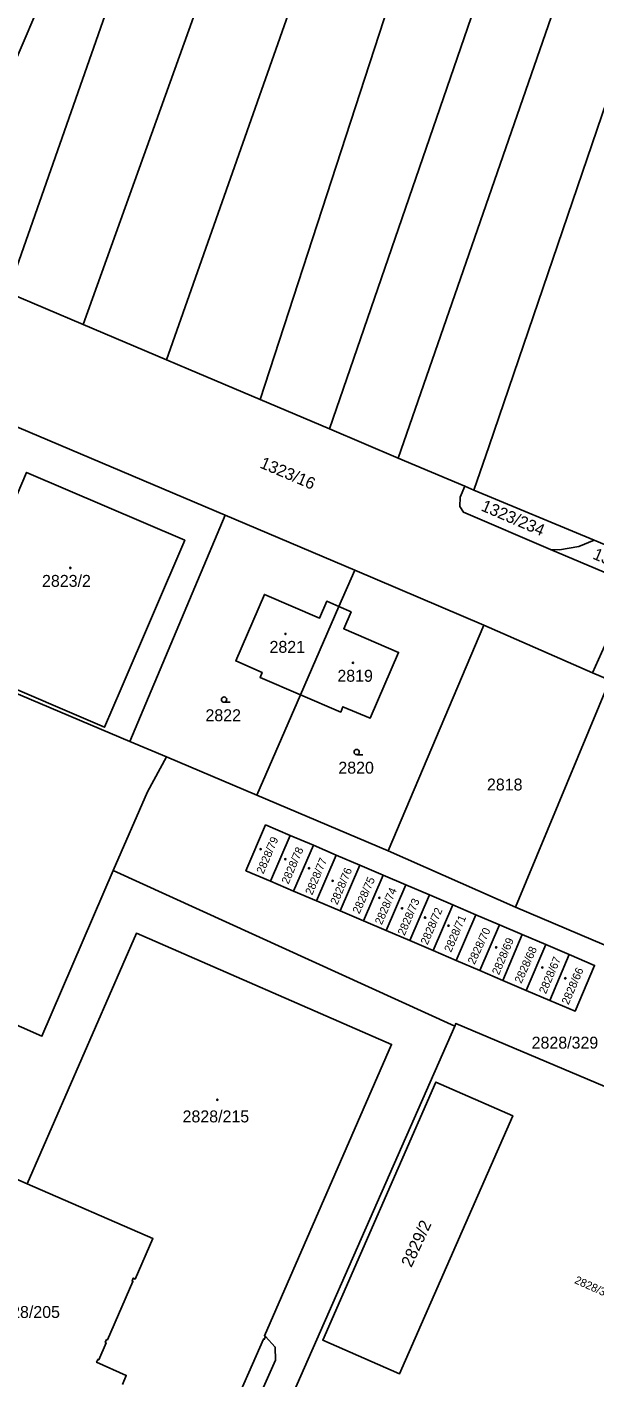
# Model space of a CAD drawing. Extents: x -596024 to -594475, y -1163820 to -1161957.
# Drawn here: x -594849.5 to -594768.7, y -1162300.1 to -1162107.7 of the extents above; entities that cross this region are included whole.
import ezdxf

# ---------------------------------------------------------------- set-up
doc = ezdxf.new("R2010")
doc.units = 0
for name, color, linetype in [('Level 1', 7, 'Continuous'), ('Level 4', 7, 'Continuous'), ('Level 5', 7, 'Continuous'), ('Level 60', 7, 'Continuous'), ('Vrstva 60', 7, 'Continuous')]:
    doc.layers.add(name, color=color, linetype=linetype)

msp = doc.modelspace()

# ---------------------------------------------------------------- linework, layer by layer
at = {"layer": 'Level 1'}
for points in [[(-594841.52, -1162150.04), (-594806.77, -1162053.21), (-594778.96, -1161974.89)], [(-594829.67, -1162155.07), (-594795.88, -1162059.09), (-594768.31, -1161981.07)], [(-594852.23, -1162145.49), (-594817.81, -1162047.12), (-594795.84, -1161983.5)], [(-594756.96, -1161987.43), (-594785.13, -1162064.92), (-594816.34, -1162160.73)], [(-594806.44, -1162164.93), (-594773.98, -1162070.58), (-594746.76, -1161991.96)], [(-594736.99, -1161996.29), (-594764.38, -1162075.96), (-594796.68, -1162169.08)], [(-594785.91, -1162173.65), (-594783.72, -1162167.34), (-594755.8, -1162085.45), (-594725.97, -1162001.77)], [(-594857.29, -1162126.68), (-594809.23, -1162014.4)], [(-594841.52, -1162150.04), (-594852.23, -1162145.49)], [(-594829.67, -1162155.07), (-594841.52, -1162150.04)], [(-594816.34, -1162160.73), (-594826.54, -1162156.4), (-594829.67, -1162155.07)], [(-594806.44, -1162164.93), (-594816.34, -1162160.73)], [(-594821.3, -1162177.21), (-594858.18, -1162161.58)], [(-594796.68, -1162169.08), (-594806.44, -1162164.93)], [(-594787.2, -1162173.1), (-594796.68, -1162169.08)], [(-594864.86, -1162177.56), (-594854.28, -1162182.09), (-594849.59, -1162171.14), (-594827.06, -1162180.8), (-594836.11, -1162201.91), (-594838.47, -1162207.42), (-594855.25, -1162200.24), (-594852.89, -1162194.72), (-594858.64, -1162192.26), (-594869.13, -1162187.77)], [(-594774.97, -1162182.11), (-594787.37, -1162176.81), (-594787.91, -1162175.99), (-594787.84, -1162174.66), (-594787.2, -1162173.1)], [(-594785.91, -1162173.65), (-594787.2, -1162173.1)], [(-594768.79, -1162180.79), (-594785.91, -1162173.65)], [(-594834.89, -1162209.45), (-594821.3, -1162177.21)], [(-594802.86, -1162185.03), (-594821.3, -1162177.21)], [(-594774.97, -1162182.11), (-594773.7, -1162182.16), (-594770.94, -1162181.7), (-594768.79, -1162180.79)], [(-594774.97, -1162182.11), (-594753.62, -1162191.15)], [(-594757.22, -1162185.61), (-594768.79, -1162180.79)], [(-594805.13, -1162190.23), (-594802.86, -1162185.03)], [(-594802.86, -1162185.03), (-594784.49, -1162192.89)], [(-594805.13, -1162190.23), (-594806.84, -1162189.49), (-594807.88, -1162191.9), (-594815.71, -1162188.51), (-594819.79, -1162197.99), (-594816.04, -1162199.63), (-594816.33, -1162200.32), (-594810.59, -1162202.79)], [(-594810.59, -1162202.79), (-594804.85, -1162205.26), (-594804.54, -1162204.52), (-594800.67, -1162206.15), (-594796.61, -1162196.78), (-594804.42, -1162193.4), (-594803.38, -1162190.99), (-594805.13, -1162190.23)], [(-594810.59, -1162202.79), (-594805.13, -1162190.23)], [(-594871.68, -1162193.87), (-594834.89, -1162209.45)], [(-594798.1, -1162225.02), (-594784.49, -1162192.89)], [(-594784.49, -1162192.89), (-594768.99, -1162199.68)], [(-594707.09, -1162223.48), (-594736.5, -1162210.95), (-594743.11, -1162207.81), (-594746.4, -1162206.15), (-594756.91, -1162200.41), (-594760.53, -1162198.75), (-594767.3, -1162195.88), (-594768.99, -1162199.68)], [(-594768.99, -1162199.68), (-594766.55, -1162200.72)], [(-594779.95, -1162233.06), (-594766.55, -1162200.72)], [(-594816.82, -1162217.1), (-594810.59, -1162202.79)], [(-594834.89, -1162209.45), (-594829.67, -1162211.66)], [(-594829.67, -1162211.66), (-594832.36, -1162216.61), (-594837.24, -1162227.82)], [(-594829.67, -1162211.66), (-594816.82, -1162217.1)], [(-594816.82, -1162217.1), (-594798.1, -1162225.02)], [(-594814.87, -1162229.35), (-594818.34, -1162227.87), (-594815.55, -1162221.34), (-594812.07, -1162222.84)], [(-594814.87, -1162229.35), (-594812.07, -1162222.84)], [(-594812.07, -1162222.84), (-594808.75, -1162224.24)], [(-594808.75, -1162224.24), (-594811.56, -1162230.76)], [(-594808.75, -1162224.24), (-594805.49, -1162225.64)], [(-594808.28, -1162232.16), (-594805.49, -1162225.64)], [(-594805.49, -1162225.64), (-594802.14, -1162227.07)], [(-594798.1, -1162225.02), (-594779.95, -1162233.06)], [(-594837.24, -1162227.82), (-594847.4, -1162251.46), (-594868.17, -1162242.29)], [(-594788.63, -1162249.99), (-594837.24, -1162227.82)], [(-594802.14, -1162227.07), (-594804.94, -1162233.59)], [(-594802.14, -1162227.07), (-594798.79, -1162228.51)], [(-594801.59, -1162235.02), (-594798.79, -1162228.51)], [(-594798.79, -1162228.51), (-594795.57, -1162229.88)], [(-594814.87, -1162229.35), (-594811.56, -1162230.76)], [(-594795.57, -1162229.88), (-594798.37, -1162236.4)], [(-594795.57, -1162229.88), (-594792.22, -1162231.31)], [(-594811.56, -1162230.76), (-594808.28, -1162232.16)], [(-594808.28, -1162232.16), (-594804.94, -1162233.59)], [(-594795.02, -1162237.83), (-594792.22, -1162231.31)], [(-594792.22, -1162231.31), (-594788.91, -1162232.73)], [(-594804.94, -1162233.59), (-594801.59, -1162235.02)], [(-594788.91, -1162232.73), (-594791.71, -1162239.25)], [(-594788.91, -1162232.73), (-594785.6, -1162234.14)], [(-594788.4, -1162240.66), (-594785.6, -1162234.14)], [(-594785.6, -1162234.14), (-594782.25, -1162235.57)], [(-594779.95, -1162233.06), (-594749.03, -1162246.2)], [(-594801.59, -1162235.02), (-594798.37, -1162236.4)], [(-594782.25, -1162235.57), (-594785.05, -1162242.09)], [(-594782.25, -1162235.57), (-594779, -1162236.97)], [(-594849.48, -1162272.49), (-594833.95, -1162236.78), (-594797.61, -1162252.61), (-594815.72, -1162294.12), (-594815.54, -1162294.21)], [(-594798.37, -1162236.4), (-594795.02, -1162237.83)], [(-594795.02, -1162237.83), (-594791.71, -1162239.25)], [(-594781.78, -1162243.49), (-594779, -1162236.97)], [(-594779, -1162236.97), (-594775.64, -1162238.4)], [(-594791.71, -1162239.25), (-594788.4, -1162240.66)], [(-594775.64, -1162238.4), (-594778.43, -1162244.92)], [(-594775.64, -1162238.4), (-594772.31, -1162239.82)], [(-594775.1, -1162246.34), (-594771.49, -1162247.88), (-594768.7, -1162241.36), (-594772.31, -1162239.82)], [(-594775.1, -1162246.34), (-594772.31, -1162239.82)], [(-594788.4, -1162240.66), (-594785.05, -1162242.09)], [(-594785.05, -1162242.09), (-594781.78, -1162243.49)], [(-594781.78, -1162243.49), (-594778.43, -1162244.92)], [(-594778.43, -1162244.92), (-594775.1, -1162246.34)], [(-594715.61, -1162280.43), (-594788.46, -1162249.61), (-594788.63, -1162249.99)], [(-594821.58, -1162324.95), (-594788.63, -1162249.99)], [(-594791.3, -1162257.98), (-594780.37, -1162262.77), (-594796.5, -1162299.54), (-594807.41, -1162294.75), (-594791.3, -1162257.98)], [(-594885.3, -1162282.79), (-594867.51, -1162290.26), (-594864.86, -1162290.92), (-594862.22, -1162289.83), (-594860.52, -1162287.62), (-594853.15, -1162270.88), (-594849.48, -1162272.49)], [(-594835.91, -1162301.05), (-594835.38, -1162299.76), (-594839.62, -1162297.9), (-594839.44, -1162297.49), (-594839.3, -1162297.55), (-594838.25, -1162295.12), (-594838.38, -1162295.06), (-594838.2, -1162294.65), (-594838.06, -1162294.71), (-594834.45, -1162286.38), (-594834.57, -1162286.32), (-594834.39, -1162285.91), (-594834.12, -1162286.03), (-594831.6, -1162280.27), (-594849.48, -1162272.49)], [(-594815.54, -1162294.21), (-594814.18, -1162295.74), (-594814.16, -1162297.59), (-594818.13, -1162306.56), (-594819.84, -1162308.09), (-594821.5, -1162308.69), (-594823.27, -1162309.05), (-594824.81, -1162308.95), (-594816.8, -1162312.43), (-594821.23, -1162322.49), (-594846.15, -1162311.6), (-594844.17, -1162307.04), (-594846.11, -1162306.5), (-594848.19, -1162306.39), (-594850.17, -1162306.87), (-594851.94, -1162307.88), (-594853.68, -1162309.72), (-594854.4, -1162311.13)], [(-594815.54, -1162294.21), (-594815.74, -1162294.63), (-594815.85, -1162294.58), (-594820.73, -1162305.71)]]:
    msp.add_lwpolyline(points, dxfattribs=at)
at = {"layer": 'Level 5'}
for p, q in [((-594821.46, -1162203.87), (-594820.58, -1162203.87)), ((-594802.58, -1162211.34), (-594801.7, -1162211.34))]:
    msp.add_line(p, q, dxfattribs=at)
for centre, radius in [((-594843.35, -1162184.73), 0.09), ((-594843.35, -1162184.73), 0.0521), ((-594812.71, -1162194.13), 0.09), ((-594812.71, -1162194.13), 0.0521), ((-594803.12, -1162198.25), 0.09), ((-594803.12, -1162198.25), 0.0521), ((-594821.46, -1162203.49), 0.375), ((-594802.58, -1162210.96), 0.375), ((-594816.25, -1162224.8), 0.09), ((-594816.25, -1162224.8), 0.0521), ((-594812.73, -1162226.22), 0.09), ((-594812.73, -1162226.22), 0.0521), ((-594809.37, -1162227.52), 0.09), ((-594809.37, -1162227.52), 0.0521), ((-594806, -1162229.31), 0.09), ((-594806, -1162229.31), 0.0521), ((-594799.36, -1162231.73), 0.09), ((-594799.36, -1162231.73), 0.0521), ((-594796.12, -1162233.23), 0.09), ((-594796.12, -1162233.23), 0.0521), ((-594792.84, -1162234.54), 0.09), ((-594792.84, -1162234.54), 0.0521), ((-594789.51, -1162235.71), 0.09), ((-594789.51, -1162235.71), 0.0521), ((-594782.72, -1162238.79), 0.09), ((-594782.72, -1162238.79), 0.0521), ((-594776.14, -1162241.66), 0.09), ((-594776.14, -1162241.66), 0.0521), ((-594772.88, -1162243.19), 0.09), ((-594772.88, -1162243.19), 0.0521), ((-594822.42, -1162260.5), 0.09), ((-594822.42, -1162260.5), 0.0521)]:
    msp.add_circle(centre, radius, dxfattribs=at)
at = {"layer": 'Level 60'}
for points in [[(-594806.77, -1162053.21), (-594841.52, -1162150.04), (-594852.23, -1162145.49), (-594817.81, -1162047.12), (-594795.84, -1161983.5), (-594789.11, -1161967.85), (-594778.96, -1161974.89)], [(-594795.88, -1162059.09), (-594829.67, -1162155.07), (-594841.52, -1162150.04), (-594806.77, -1162053.21), (-594778.96, -1161974.89), (-594768.31, -1161981.07)], [(-594768.31, -1161981.07), (-594756.96, -1161987.43), (-594785.13, -1162064.92), (-594816.34, -1162160.73), (-594826.54, -1162156.4), (-594829.67, -1162155.07), (-594795.88, -1162059.09)], [(-594817.81, -1162047.12), (-594852.23, -1162145.49), (-594862.25, -1162141.24), (-594857.29, -1162126.68), (-594809.23, -1162014.4), (-594795.84, -1161983.5)], [(-594806.44, -1162164.93), (-594816.34, -1162160.73), (-594785.13, -1162064.92), (-594756.96, -1161987.43), (-594746.76, -1161991.96), (-594773.98, -1162070.58)], [(-594736.99, -1161996.29), (-594764.38, -1162075.96), (-594796.68, -1162169.08), (-594806.44, -1162164.93), (-594773.98, -1162070.58), (-594746.76, -1161991.96)], [(-594861.45, -1162136.02), (-594935.08, -1162105.7), (-594930.49, -1162089.91), (-594898.57, -1162015.96), (-594890.22, -1161996.88), (-594874.7, -1162003.85), (-594838.41, -1162020.17), (-594830.59, -1162006.94), (-594829.79, -1162005.61), (-594809.23, -1162014.4), (-594857.29, -1162126.68)], [(-594755.8, -1162085.45), (-594783.72, -1162167.34), (-594785.91, -1162173.65), (-594787.2, -1162173.1), (-594796.68, -1162169.08), (-594764.38, -1162075.96), (-594736.99, -1161996.29), (-594725.97, -1162001.77)], [(-594783.72, -1162167.34), (-594755.8, -1162085.45), (-594725.97, -1162001.77), (-594686.86, -1162020.42), (-594715.97, -1162103.7), (-594744.22, -1162183.48), (-594746.55, -1162190.06), (-594757.22, -1162185.61), (-594768.79, -1162180.79), (-594785.91, -1162173.65)], [(-594827.06, -1162180.8), (-594849.59, -1162171.14), (-594854.28, -1162182.09), (-594864.86, -1162177.56), (-594858.18, -1162161.58), (-594821.3, -1162177.21), (-594834.89, -1162209.45), (-594871.68, -1162193.87), (-594869.13, -1162187.77), (-594858.64, -1162192.26), (-594852.89, -1162194.72), (-594855.25, -1162200.24), (-594838.47, -1162207.42), (-594836.11, -1162201.91)], [(-594849.59, -1162171.14), (-594827.06, -1162180.8), (-594836.11, -1162201.91), (-594838.47, -1162207.42), (-594855.25, -1162200.24), (-594852.89, -1162194.72), (-594858.64, -1162192.26), (-594869.13, -1162187.77), (-594864.86, -1162177.56), (-594854.28, -1162182.09)], [(-594787.37, -1162176.81), (-594787.91, -1162175.99), (-594787.84, -1162174.66), (-594787.2, -1162173.1), (-594785.91, -1162173.65), (-594768.79, -1162180.79), (-594770.94, -1162181.7), (-594773.7, -1162182.16), (-594774.97, -1162182.11)], [(-594871.68, -1162193.87), (-594834.89, -1162209.45), (-594829.67, -1162211.66), (-594832.36, -1162216.61), (-594837.24, -1162227.82), (-594847.4, -1162251.46), (-594868.17, -1162242.29), (-594910.96, -1162223.4), (-594905.52, -1162210.83), (-594912.71, -1162195.25), (-594916.76, -1162183.81), (-594914.71, -1162178.11)], [(-594815.71, -1162188.51), (-594819.79, -1162197.99), (-594816.04, -1162199.63), (-594816.33, -1162200.32), (-594810.59, -1162202.79), (-594816.82, -1162217.1), (-594829.67, -1162211.66), (-594834.89, -1162209.45), (-594821.3, -1162177.21), (-594802.86, -1162185.03), (-594805.13, -1162190.23), (-594806.84, -1162189.49), (-594807.88, -1162191.9)], [(-594774.97, -1162182.11), (-594773.7, -1162182.16), (-594770.94, -1162181.7), (-594768.79, -1162180.79), (-594757.22, -1162185.61), (-594757.06, -1162186.25), (-594755.77, -1162188.82), (-594753.62, -1162191.15)], [(-594804.85, -1162205.26), (-594804.54, -1162204.52), (-594800.67, -1162206.15), (-594796.61, -1162196.78), (-594804.42, -1162193.4), (-594803.38, -1162190.99), (-594805.13, -1162190.23), (-594802.86, -1162185.03), (-594784.49, -1162192.89), (-594798.1, -1162225.02), (-594816.82, -1162217.1), (-594810.59, -1162202.79)], [(-594819.79, -1162197.99), (-594815.71, -1162188.51), (-594807.88, -1162191.9), (-594806.84, -1162189.49), (-594805.13, -1162190.23), (-594810.59, -1162202.79), (-594816.33, -1162200.32), (-594816.04, -1162199.63)], [(-594804.54, -1162204.52), (-594804.85, -1162205.26), (-594810.59, -1162202.79), (-594805.13, -1162190.23), (-594803.38, -1162190.99), (-594804.42, -1162193.4), (-594796.61, -1162196.78), (-594800.67, -1162206.15)], [(-594784.49, -1162192.89), (-594768.99, -1162199.68), (-594766.55, -1162200.72), (-594779.95, -1162233.06), (-594798.1, -1162225.02)], [(-594702.53, -1162225.59), (-594699.9, -1162227.48), (-594697.92, -1162229.81), (-594735.81, -1162213.85), (-594766.55, -1162200.72), (-594768.99, -1162199.68), (-594767.3, -1162195.88), (-594760.53, -1162198.75), (-594756.91, -1162200.41), (-594746.4, -1162206.15), (-594743.11, -1162207.81), (-594736.5, -1162210.95), (-594707.09, -1162223.48)], [(-594735.81, -1162213.85), (-594736.56, -1162215.7), (-594749.03, -1162246.2), (-594779.95, -1162233.06), (-594766.55, -1162200.72)], [(-594816.82, -1162217.1), (-594798.1, -1162225.02), (-594779.95, -1162233.06), (-594749.03, -1162246.2), (-594708.5, -1162263.93), (-594715.61, -1162280.43), (-594788.46, -1162249.61), (-594788.63, -1162249.99), (-594837.24, -1162227.82), (-594832.36, -1162216.61), (-594829.67, -1162211.66)], [(-594818.34, -1162227.87), (-594814.87, -1162229.35), (-594811.56, -1162230.76), (-594808.28, -1162232.16), (-594804.94, -1162233.59), (-594801.59, -1162235.02), (-594798.37, -1162236.4), (-594795.02, -1162237.83), (-594791.71, -1162239.25), (-594788.4, -1162240.66), (-594785.05, -1162242.09), (-594781.78, -1162243.49), (-594778.43, -1162244.92), (-594775.1, -1162246.34), (-594771.49, -1162247.88), (-594768.7, -1162241.36), (-594772.31, -1162239.82), (-594775.64, -1162238.4), (-594779, -1162236.97), (-594782.25, -1162235.57), (-594785.6, -1162234.14), (-594788.91, -1162232.73), (-594792.22, -1162231.31), (-594795.57, -1162229.88), (-594798.79, -1162228.51), (-594802.14, -1162227.07), (-594805.49, -1162225.64), (-594808.75, -1162224.24), (-594812.07, -1162222.84), (-594815.55, -1162221.34)], [(-594812.07, -1162222.84), (-594814.87, -1162229.35), (-594818.34, -1162227.87), (-594815.55, -1162221.34)], [(-594808.75, -1162224.24), (-594811.56, -1162230.76), (-594814.87, -1162229.35), (-594812.07, -1162222.84)], [(-594805.49, -1162225.64), (-594808.28, -1162232.16), (-594811.56, -1162230.76), (-594808.75, -1162224.24)], [(-594802.14, -1162227.07), (-594804.94, -1162233.59), (-594808.28, -1162232.16), (-594805.49, -1162225.64)], [(-594798.79, -1162228.51), (-594801.59, -1162235.02), (-594804.94, -1162233.59), (-594802.14, -1162227.07)], [(-594795.57, -1162229.88), (-594798.37, -1162236.4), (-594801.59, -1162235.02), (-594798.79, -1162228.51)], [(-594792.22, -1162231.31), (-594795.02, -1162237.83), (-594798.37, -1162236.4), (-594795.57, -1162229.88)], [(-594788.91, -1162232.73), (-594791.71, -1162239.25), (-594795.02, -1162237.83), (-594792.22, -1162231.31)], [(-594785.6, -1162234.14), (-594788.4, -1162240.66), (-594791.71, -1162239.25), (-594788.91, -1162232.73)], [(-594782.25, -1162235.57), (-594785.05, -1162242.09), (-594788.4, -1162240.66), (-594785.6, -1162234.14)], [(-594779, -1162236.97), (-594781.78, -1162243.49), (-594785.05, -1162242.09), (-594782.25, -1162235.57)], [(-594775.64, -1162238.4), (-594778.43, -1162244.92), (-594781.78, -1162243.49), (-594779, -1162236.97)], [(-594772.31, -1162239.82), (-594775.1, -1162246.34), (-594778.43, -1162244.92), (-594775.64, -1162238.4)], [(-594775.1, -1162246.34), (-594772.31, -1162239.82), (-594768.7, -1162241.36), (-594771.49, -1162247.88)], [(-594788.46, -1162249.61), (-594715.61, -1162280.43), (-594744.57, -1162347.6), (-594746.96, -1162353.57), (-594748.04, -1162354.24), (-594750.51, -1162354.75), (-594752.49, -1162354.29), (-594804.19, -1162332.35), (-594810.1, -1162329.79), (-594821.58, -1162324.95), (-594788.63, -1162249.99)], [(-594780.37, -1162262.77), (-594791.3, -1162257.98), (-594807.41, -1162294.75), (-594796.5, -1162299.54)], [(-594791.3, -1162257.98), (-594780.37, -1162262.77), (-594796.5, -1162299.54), (-594807.41, -1162294.75)]]:
    msp.add_lwpolyline(points, close=True, dxfattribs=at)
for points in [[(-594868.17, -1162242.29), (-594847.4, -1162251.46), (-594837.24, -1162227.82), (-594788.63, -1162249.99), (-594821.58, -1162324.95), (-594854.4, -1162311.13)], [(-594850.17, -1162306.87), (-594848.19, -1162306.39), (-594846.11, -1162306.5), (-594844.17, -1162307.04), (-594846.15, -1162311.6), (-594821.23, -1162322.49), (-594816.8, -1162312.43), (-594824.81, -1162308.95), (-594823.27, -1162309.05), (-594821.5, -1162308.69), (-594819.84, -1162308.09), (-594818.13, -1162306.56), (-594814.16, -1162297.59), (-594814.18, -1162295.74), (-594815.54, -1162294.21), (-594815.72, -1162294.12), (-594797.61, -1162252.61), (-594833.95, -1162236.78), (-594849.48, -1162272.49), (-594853.15, -1162270.88)], [(-594835.91, -1162301.05), (-594835.38, -1162299.76), (-594839.62, -1162297.9), (-594839.44, -1162297.49), (-594839.3, -1162297.55), (-594838.25, -1162295.12), (-594838.38, -1162295.06), (-594838.2, -1162294.65), (-594838.06, -1162294.71), (-594834.45, -1162286.38), (-594834.57, -1162286.32), (-594834.39, -1162285.91), (-594834.12, -1162286.03), (-594831.6, -1162280.27), (-594849.48, -1162272.49), (-594833.95, -1162236.78), (-594797.61, -1162252.61), (-594815.72, -1162294.12), (-594815.54, -1162294.21), (-594815.74, -1162294.63), (-594815.85, -1162294.58), (-594820.73, -1162305.71)], [(-594853.15, -1162270.88), (-594849.48, -1162272.49), (-594831.6, -1162280.27), (-594834.12, -1162286.03), (-594834.39, -1162285.91), (-594834.57, -1162286.32), (-594834.45, -1162286.38), (-594838.06, -1162294.71), (-594838.2, -1162294.65), (-594838.38, -1162295.06), (-594838.25, -1162295.12), (-594839.3, -1162297.55), (-594839.44, -1162297.49), (-594839.62, -1162297.9), (-594835.38, -1162299.76), (-594835.91, -1162301.05)], [(-594820.73, -1162305.71), (-594815.85, -1162294.58), (-594815.74, -1162294.63), (-594815.54, -1162294.21), (-594814.18, -1162295.74), (-594814.16, -1162297.59), (-594818.13, -1162306.56)]]:
    msp.add_lwpolyline(points, dxfattribs=at)
at = {"layer": 'Vrstva 60'}
for points in [[(-594629.59, -1162242.59), (-594657.76, -1162230.53), (-594675.03, -1162223.23), (-594709.6, -1162209.52), (-594727.84, -1162201.98), (-594745.73, -1162194.48), (-594753.62, -1162191.15), (-594774.97, -1162182.11), (-594787.37, -1162176.81), (-594787.91, -1162175.99), (-594787.84, -1162174.66), (-594787.2, -1162173.1), (-594796.68, -1162169.08), (-594806.44, -1162164.93), (-594816.34, -1162160.73), (-594826.54, -1162156.4), (-594829.67, -1162155.07), (-594841.52, -1162150.04), (-594852.23, -1162145.49)], [(-594858.18, -1162161.58), (-594821.3, -1162177.21), (-594802.86, -1162185.03), (-594784.49, -1162192.89), (-594768.99, -1162199.68), (-594767.3, -1162195.88), (-594760.53, -1162198.75), (-594756.91, -1162200.41), (-594746.4, -1162206.15), (-594743.11, -1162207.81), (-594736.5, -1162210.95), (-594707.09, -1162223.48), (-594665.22, -1162239.43), (-594660.59, -1162241.27), (-594597.6, -1162268.15)]]:
    msp.add_lwpolyline(points, dxfattribs=at)

# ---------------------------------------------------------------- texts
at = {"layer": 'Level 4'}
for s, height, rotation, p in [('1323/16', 1.7, 336.9981, (-594816.49, -1162170.41)), ('1323/234', 1.7, 336.8572, (-594784.99, -1162176.52)), ('1323/233', 1.7, 337.0513, (-594769.09, -1162183.38)), ('2828/79', 1.14, 66.7271, (-594815.87, -1162228.41)), ('2828/78', 1.14, 66.6849, (-594812.3, -1162229.87)), ('2828/77', 1.14, 66.8332, (-594808.92, -1162231.42)), ('2828/76', 1.14, 67.1927, (-594805.34, -1162232.81)), ('2828/75', 1.14, 65.7, (-594802.2, -1162234.1)), ('2828/74', 1.14, 66.759, (-594799.01, -1162235.66)), ('2828/73', 1.14, 66.759, (-594795.76, -1162237.19)), ('2828/72', 1.14, 66.759, (-594792.5, -1162238.51)), ('2828/71', 1.14, 66.759, (-594789.14, -1162239.57)), ('2828/70', 1.14, 65.0261, (-594785.81, -1162241.32)), ('2828/69', 1.14, 66.9075, (-594782.33, -1162242.8)), ('2828/68', 1.14, 65.7, (-594779.14, -1162244.01)), ('2828/67', 1.14, 66.8332, (-594775.64, -1162245.5)), ('2828/66', 1.14, 66.8332, (-594772.42, -1162247.04)), ('2829/2', 1.7, 65.2878, (-594794.79, -1162284.48)), ('2828/333', 1.14, 335.8, (-594771.67, -1162286.58))]:
    msp.add_text(s, height=height, rotation=rotation, dxfattribs=at).set_placement(p)
for s, p in [('2823/2', (-594847.38, -1162187.43)), ('2821', (-594814.99, -1162196.83)), ('2819', (-594805.33, -1162200.95)), ('2822', (-594824.11, -1162206.57)), ('2820', (-594805.19, -1162214.04)), ('2818', (-594784.03, -1162216.44)), ('2828/329', (-594777.67, -1162253.21)), ('2828/215', (-594827.37, -1162263.72)), ('2828/205', (-594854.31, -1162291.58))]:
    msp.add_text(s, height=1.7, dxfattribs=at).set_placement(p)

doc.saveas('drawing.dxf')
